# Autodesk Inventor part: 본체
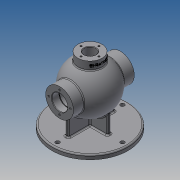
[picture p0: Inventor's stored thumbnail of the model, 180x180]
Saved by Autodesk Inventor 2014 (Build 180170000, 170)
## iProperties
Created: 2020-08
Part Number: 본체
Material: Generic
Document SubType Name: Modeling
Designer: kb542
Density: 1 g/cm^3
Appearance: Default
Author: kb542
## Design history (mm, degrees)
sketch "스케치1"
  geometry: L1 (0, 1783.933)-(0, 0); L2 (0, 0)-(1727.2, 0); L3 (1727.2, 0)-(1727.2, 787.4); L4 (1727.2, 787.4)-(1123.071, 787.4); L5 (997.658, 444.5)-(1727.2, 444.5); A1 r 1371.6 centre (0, 0) between (1123.071, 787.4) and (0, 1371.6); A2 r 1092.2 centre (0, 0) between (997.658, 444.5) and (0, 1092.2); 1 further point
  constraints: 10 end point, 4 point on circle, 3 coincident, 3 perpendicular, 3 point on line, 2 centre point, 1 parallel, 1 vertical
  dimensions: "d0" = 3454.4 diameter of L3 L1; "d1" = 1574.8 diameter of L4 L2; "d2" = 2743.2 diameter of A1; "d4" = 2184.4 diameter of A2; "d5" = 889 diameter of L5 L2
revolve "회전1" sketch "스케치1" stored, may be unused: angle "d6" = 90 deg
node "작업 평면1"
sketch "스케치4"
  geometry: C1 r 2159 at (0, 0); 1 further point
  constraints: 1 centre point, 1 coincident
  dimensions: "d25" = 4318 diameter of C1
extrude "돌출1" join sketch "스케치4" distance "d26" = 254; taper "d27" = 0 deg
sketch "스케치5"
  geometry: L1 (-1320.8, 101.6)-(1320.8, 101.6); L2 (1320.8, 101.6)-(1320.8, -101.6); L3 (1320.8, -101.6)-(-1320.8, -101.6); L4 (-1320.8, -101.6)-(-1320.8, 101.6); L5 (-101.6, 1092.2)-(101.6, 1092.2); L6 (101.6, 1092.2)-(101.6, -1092.2); L7 (101.6, -1092.2)-(-101.6, -1092.2); L8 (-101.6, -1092.2)-(-101.6, 1092.2); C1 r 2159 at (0, 0) reference; 4 further points
  constraints: 16 end point, 4 midpoint, 4 parallel, 2 horizontal, 2 horizontal alignment, 2 perpendicular, 2 vertical alignment
  dimensions: "d28" = 2641.6 distance between parallel lines of L2 L4; "d29" = 203.2 distance between parallel lines of L3 L1; "d30" = 203.2 distance between parallel lines of L6 L8; "d31" = 2184.4 distance between parallel lines of L7 L5
extrude "돌출2" join sketch "스케치5" stored distance "d32" = 254; taper "d33" = 0 deg
fillet "모깎기1" dims "d42" = 76.2
fillet "모깎기2" dims "d43" = 76.2
node "작업 평면2"
sketch "스케치8"
  geometry: C1 r 685.8 at (0, 0); 1 further point
  constraints: 1 centre point, 1 coincident
  dimensions: "d46" = 1371.6 diameter of C1
extrude "돌출3" join sketch "스케치8" stored distance "d47" = 254; taper "d48" = 0 deg
sketch "스케치9"
  geometry: C1 r 685.8 at (0, 0) reference; C2 r 330.2 at (0, 0)
  constraints: 1 centre point, 1 coincident
  dimensions: "d49" = 660.4 diameter of C2
extrude "돌출4" cut sketch "스케치9" stored distance "d50" = 254; taper "d51" = 0 deg
chamfer "모따기1" distance "d52" = 25.4; stored, may be unused: second distance "d53" = 3.175, angle "d54" = 45 deg
chamfer "모따기2" distance "d55" = 25.4; stored, may be unused: second distance "d56" = 3.175, angle "d57" = 45 deg
chamfer "모따기3" distance "d58" = 25.4; stored, may be unused: second distance "d59" = 3.175, angle "d60" = 45 deg
node "작업 평면3"
sketch "스케치10"
  geometry: L1 (-685.8, 1651)-(-685.8, 1187.84) reference; L2 (685.8, 1651)-(685.8, 1187.84) reference; L3 (685.8, 1651)-(-685.8, 1651) reference; 2 further points
  constraints: 1 other
  dimensions: "d62" = 685.8 distance from line of point (0, 1422.4) L1; "d63" = 228.6 distance from line of point (0, 1422.4) L3
feature "엠보싱1" sketch "스케치10" dims "d0" = 3454.4, "d1" = 1574.8, "d2" = 2743.2, "d4" = 2184.4, "d5" = 889, "d64" = 12.7, "d65" = 0
sketch "스케치11" dims "d66" = 1016
  geometry: C1 r 355.6 at (0, 0) reference; C2 r 50.8 at (0, 508); 2 further points
  constraints: 2 coincident, 1 centre point, 1 vertical alignment, 2 other
  dimensions: "d67" = 101.6 diameter of C2
hole "구멍4" sketch "스케치11" at (0, 508) diameter "d68" = 101.7524; stored, may be unused: countersink angle "d72" = 82 deg, drill point angle "d74" = 118 deg; dims "d69" = 304.8, "d70" = 3.0226, "d71" = 6.35, "d73" = 381
sketch "스케치12"
  geometry: C1 r 469.9 at (0, 0) reference; A1 r 609.6 centre (0, 0) between (0, 609.6) and (609.6, 0); 2 further points
  constraints: 4 point on circle, 1 centre point, 1 coincident
  dimensions: "d78" = 1219.2 diameter of A1
hole "구멍5" sketch "스케치12" at (0, 609.6), (609.6, 0), (0, -609.6), (-609.6, 0) diameter "d79" = 101.7524; stored, may be unused: countersink angle "d83" = 82 deg, drill point angle "d85" = 118 deg; dims "d80" = 304.8, "d81" = 3.0226, "d82" = 6.35, "d84" = 381
node "작업 평면4"
sketch "스케치13"
  geometry: C1 r 469.9 at (0, 0); 1 further point
  constraints: 1 centre point, 1 coincident
  dimensions: "d87" = 939.8 diameter of C1
extrude "돌출5" cut sketch "스케치13" distance "d88" = 44.45; taper "d89" = 0 deg
fillet "모깎기3" dims "d90" = 76.2
sketch "스케치14"
  geometry: C1 r 2082.8 at (0, 0) reference; C2 r 114.3 at (0, 1841.5); C3 r 114.3 at (1841.5, 0); C4 r 114.3 at (0, -1841.5); C5 r 114.3 at (-1841.5, 0); A1 r 1841.5 centre (0, 0) between (0, 1841.5) and (1841.5, 0)
  constraints: 5 centre point, 4 point on circle, 1 coincident, 1 horizontal alignment
  dimensions: "d91" = 3683 diameter of A1; "d92" = 228.6 diameter of C2; "d93" = 228.6 diameter of C3; "d94" = 228.6 diameter of C4; "d95" = 228.6 diameter of C5
extrude "돌출6" cut sketch "스케치14" stored distance "d96" = 44.45; taper "d97" = 0 deg
node "솔리드1"
mirror "대칭1"
pattern_circular "원형 패턴1" dims angle "d76" = 360 deg
mirror "대칭2"
other parameters: "d24" = -2159, "d61" = -685.8, "d86" = -406.4
